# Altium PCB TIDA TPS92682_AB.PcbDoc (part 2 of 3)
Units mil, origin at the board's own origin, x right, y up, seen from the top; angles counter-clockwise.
Board outline 3149 x 2999 mil, 6 copper layers (Top Layer, Signal Layer 1, Signal Layer 2, Signal Layer 3, Signal Layer 4, Bottom Layer), stack 61.4 mil thick; 281 components, 181 nets, 796 pads, 814 vias.
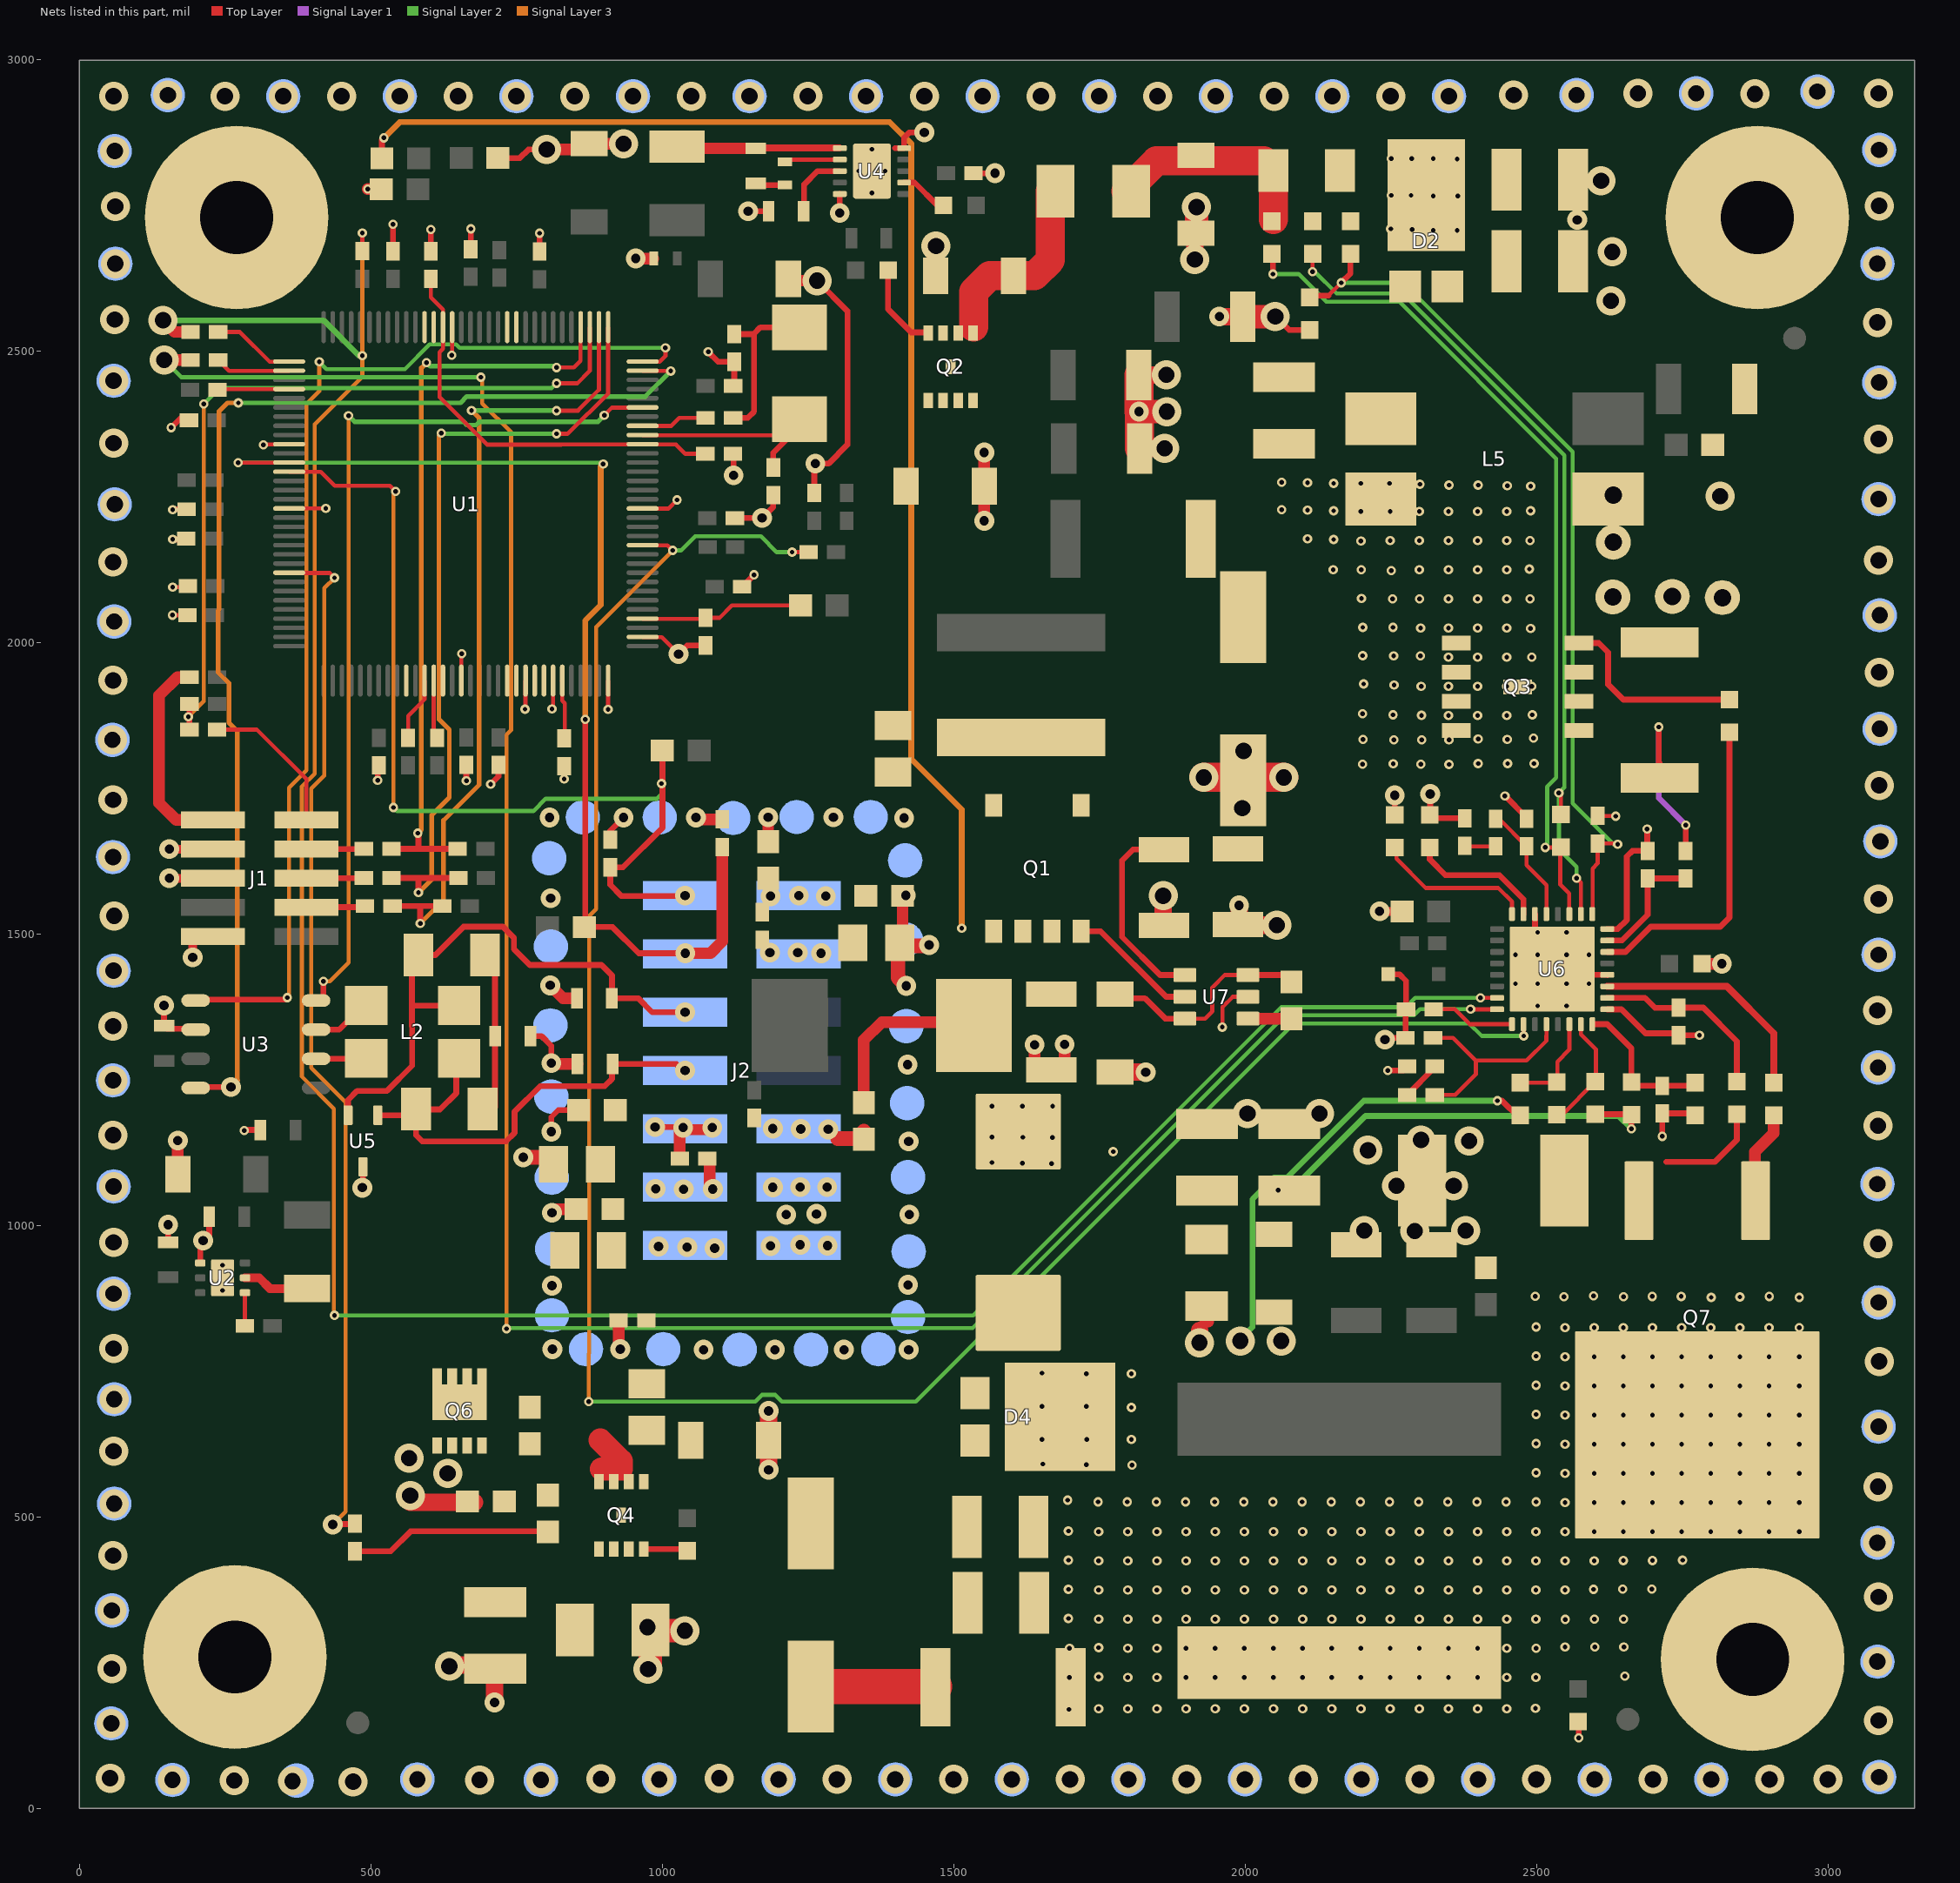
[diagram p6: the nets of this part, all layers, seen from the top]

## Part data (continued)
C90: library part CMP-0006993-4, "CAP, CERM, 1000 pF, 100 V, +/- 5%, C0G/NP0, 0603", Cap_Case=0603, Manufacturer=TDK, PartNumber=C1608C0G2A102J080AA, Supplier Part Number 1=445-2312-1-ND, TempCo=C0G/NP0, Tolerance_%=5%, Value1="0.0589 ohm", Value2=100V, ValueDisplayed=1nF
D2: library part CMP-0028754-2, "Diode, Schottky, 100 V, 3 A, AEC-Q101, PowerDI5", Manufacturer="Diodes Inc.", Value1=3A, Value2=0.76V
D3: library part CMP-0085730-1, "Diode, Zener, 3.3 V, 300 mW, AEC-Q101, SOD-323", Manufacturer="ON Semiconductor", Power_W=300mW, Value1=0.3W
D4: library part CMP-0028826-1, "Diode, Schottky, 100 V, 8 A, AEC-Q101, TO-277A", Manufacturer="Fairchild Semiconductor", Supplier Part Number 1=FSV8100VCT-ND, Value1=8A, Value2=0.67V
FID1 FID2 FID3: library part CMP-0077181-1, "Fiducial mark.  There is nothing to buy or mount.", Manufacturer=N/A
J1: library part CMP-0075629-2, "Header, 1.27mm, 5x2, Gold, Black, SMT", Color=Black, Current_A=3.3A, Manufacturer=Samtec, PartNumber=FTSH-105-01-F-DV, Supplier Part Number 1=SAM8795-ND
J2: library part CMP-0075611-2, "Header, 2.54mm, 7x2, Gold, SMT", Color=Black, Current_A=5.4A, Manufacturer=Samtec, Supplier Part Number 1=TSM-107-01-L-DV-ND
L1: library part CMP-0062763-1, "Inductor, Wirewound, Ferrite, 1 uH, 1 A, 0.06 ohm, SMD", Manufacturer=TDK, PartNumber=NLCV32T-1R0M-PF, Supplier Part Number 1=445-1534-1-ND, Value1="0.06 ohm", Value2=1A, ValueDisplayed=1uH
L2: library part CMP-0076842-1, "Coupled inductor, 100 µH, 0.15 A, 1.5 ohm, SMD", Manufacturer=TDK, PartNumber=B82789C0104H001, Supplier Part Number 1=871-B82789C0104H001, ValueDisplayed=100µH
L3: library part CMP-0058987-1, "Inductor, Shielded, 4.7 uH, 2.7 A, 0.083 ohm, AEC-Q200 Grade 1, SMD", Manufacturer="MuRata Toko", Value1="0.083 ohm", Value2=2.7A, ValueDisplayed=4.7uH
L4: library part CMP-0061052-1, "Inductor, Shielded, Composite, 3.3 uH, 15.1 A, 0.01 ohm, SMD", Manufacturer=Coilcraft, Value1="0.01 ohm", Value2=15.1A, ValueDisplayed=3.3uH
L5: library part CMP-0013101-2, "Coupled inductor, 15 uH, 6.5 A, 0.0355 ohm, SMD", Manufacturer=TDK, PartNumber=B82477D4153M000, Supplier Part Number 1=2254607, ValueDisplayed=15uH
L6 L10: library part CMP-0063280-1, "Inductor, Shielded Drum Core, Powdered Iron, 4.7 uH, 1.7 A, 0.095 ohm, SMD", Manufacturer=Vishay-Dale, Supplier Part Number 1=541-1051-1-ND, Value1="0.095 ohm", Value2=1.7A, ValueDisplayed=4.7uH
L7 L11 L12 L13 L14: library part CMP-0003297-1, "Ferrite Bead, 220 ohm @ 100 MHz, 2 A, 0805", Manufacturer="Wurth Elektronik", Supplier Part Number 1=732-6711-1-ND, Value1="0.05 ohm", Value2=2A, ValueDisplayed="220 ohm"
L8: library part CMP-0061646-2, "Inductor, Shielded, Composite, 15 uH, 18 A, 0.00917 ohm, SMD", Manufacturer=Coilcraft, Value1="0.00917 ohm", Value2=18A, ValueDisplayed=15uH
L9: library part CMP-0080422-3, "Inductor, Shielded, Ferrite, 15 µH, 3.3 A, 0.036 ohm, AEC-Q200 Grade 0, SMD", Manufacturer=TDK, Supplier Part Number 1=445-174717-1-ND, Value1="0.036 ohm", Value2=3.3A, ValueDisplayed=15µH
L15: library part CMP-0003060-1, "Ferrite Bead, 115 ohm @ 100 MHz, 10 A, SMD, 2-Leads, Body 8.74x4.65mm", Manufacturer="Laird-Signal Integrity Products", Supplier Part Number 1=240-2511-1-ND, Value1="0.001 ohm", Value2=10A, ValueDisplayed="115 ohm"
LBL1: library part CMP-0003625-1, "Thermal Transfer Printable Labels, 0.650\" W x 0.200\" H - 10,000 per roll", Manufacturer=Brady, Supplier Part Number 1=97C5133
Logo1: library part CMP-0074844-1
Logo2: library part CMP-0074838-1, "Texas Instrument Corporate Signature"
Logo3: library part CMP-0074847-1, "FCC_disclaimer"
Logo4: library part CMP-0074769-1
Logo5: library part CMP-0074836-1, "IEC 61010-1 Caution Warning"
LOGO6: library part CMP-0074837-1, "IEC 61010-1 Hot Surface Warning"
Q1: library part CMP-0077633-1, "MOSFET, N-CH, 60 V, 287 A, AEC-Q101, DFN5 5x6mm", Alternate Manufacturer=None, Manufacturer="ON Semiconductor", Supplier Part Number 1=NVMFS5C604NLT1G-ND, Value1="0.0017 ohm", Value2="52 nC"
Q2 Q4: library part CMP-0750095-1, "MOSFET, P-CH, -60 V, -6 A, AEC-Q101, 8-PowerWDFN", Alternate Manufacturer=None, Manufacturer="ON Semiconductor", Value1="0.072 ohm", Value2="14 nC"
Q3: library part CMP-0001033-3, "MOSFET, N-CH, 100 V, 20 A, AEC-Q101, 8-PowerVDFN", Alternate Manufacturer=None, Manufacturer=STMicroelectronics, Supplier Part Number 1=497-13652-1-ND, Value2="20.5 nC"
Q6: library part CMP-0000970-2, "MOSFET, N-CH, 100 V, 3.8 A, 8-PowerVDFN", Alternate Manufacturer=None, Manufacturer="Diodes Inc.", PartNumber=DMN10H120SFG-13, Supplier Part Number 1=DMN10H120SFG-13DICT-ND, Value2="10.6 nC"
Q7: library part CMP-0082013-2, "MOSFET, N-CH, 80 V, 75 A, AEC-Q101, DDPAK", Alternate Manufacturer=None, Manufacturer=Nexperia, Supplier Part Number 1=1727-1093-1-ND, Value1="? ohm", Value2="48.8 nC"
R1: library part CMP-0026763-1, "RES, 100, 1%, 0.063 W, AEC-Q200 Grade 0, 0402", Manufacturer="Stackpole Electronics Inc", Power_W=63mW, Supplier Part Number 1=RMCF0402JT100RCT-ND, TempCo="100 ppm/C", Tolerance_%=1%, Value2=0.063W, Value_Code=100R, ValueDisplayed=100
R2 R3 R8 R13 R26 R28 R44 R45 R72: library part CMP-0026754-1, "RES, 10.0 k, 1%, 0.063 W, AEC-Q200 Grade 0, 0402", Manufacturer="Stackpole Electronics Inc", Power_W=63mW, Supplier Part Number 1=RMCF0402FT10K0CT-ND, TempCo="100 ppm/C", Tolerance_%=1%, Value2=0.063W, Value_Code=10k0, ValueDisplayed=10.0k
R4 R5 R6 R7 R59 R60 R61 R62 R63 R71: library part CMP-0026759-1, "RES, 33.0, 1%, 0.063 W, AEC-Q200 Grade 0, 0402", Manufacturer="Stackpole Electronics Inc", Power_W=63mW, Supplier Part Number 1=RMCF0402FT33R0CT-ND, TempCo="100 ppm/C", Tolerance_%=1%, Value2=0.063W, Value_Code=33R0, ValueDisplayed=33.0
R9: library part CMP-0025825-4, "RES, 51, 5%, 0.1 W, AEC-Q200 Grade 0, 0603", Manufacturer=Vishay-Dale, PartNumber=CRCW060351R0JNEA, Power_W=100mW, Supplier Part Number 1=541-51GCT-ND, TempCo="200 ppm/C", Tolerance_%=5%, Value2=0.1W, Value_Code=51R0, ValueDisplayed=51
R10 R18: library part CMP-0026825-5, "RES, 10 k, 5%, 0.063 W, AEC-Q200 Grade 0, 0402", Manufacturer=Vishay-Dale, PartNumber=CRCW040210K0JNED, Power_W=63mW, Supplier Part Number 1=541-10KJCT-ND, TempCo="200 ppm/C", Tolerance_%=5%, Value2=0.063W, Value_Code=10k0, ValueDisplayed=10k
R14 R39 R43 R70: library part CMP-0025950-3, "RES, 100 k, 1%, 0.063 W, AEC-Q200 Grade 0, 0402", Manufacturer=Vishay-Dale, Power_W=63mW, Supplier Part Number 1=541-100KLCT-ND, TempCo="100 ppm/C", Tolerance_%=1%, Value2=0.063W, Value_Code=100k
R16: library part CMP-0026781-1, "RES, 4.87 k, 0.1%, 0.062 W, AEC-Q200 Grade 0, 0402", Manufacturer=Panasonic, Power_W=62mW, Supplier Part Number 1=P4.87KDCCT-ND, TempCo="25 ppm/C", Tolerance_%=0.1%, Value2=0.062W, Value_Code=4k87, ValueDisplayed=4.87k
R17: library part CMP-0026992-3, "RES, 0, 5%, 0.1 W, AEC-Q200 Grade 0, 0402", Manufacturer=Panasonic, PartNumber=ERJ-2GE0R00X, Power_W=100mW, Supplier Part Number 1=P0.0JCT-ND, TempCo="600 ppm/C", Tolerance_%=5%, Value2=0.1W, Value_Code=0000, ValueDisplayed=0
R19: library part CMP-0015792-2, "RES, 0.1, 1%, 2 W, 2512", Manufacturer="Stackpole Electronics Inc", Power_W=2W, Supplier Part Number 1=CSRN2512FTR100CT-ND, TempCo="200 ppm/C", Tolerance_%=1%, Value_Code=R100, ValueDisplayed=0.1
R20: library part CMP-0002354-3, "Thermistor NTC, 100k ohm, 1%, 0603", Manufacturer=TDK, PartNumber=NTCG164KF104F, Supplier Part Number 1=445-2556-1-ND, Tolerance_%=1%
R21 R37 R55: library part CMP-0022986-5, "RES, 2.20 k, 1%, 0.1 W, 0603", Manufacturer=Yageo, PartNumber=RC0603FR-072K2L, Power_W=100mW, Supplier Part Number 1=311-2.20KHRCT-ND, TempCo="100 ppm/C", Tolerance_%=1%, Value2=0.1W, Value_Code=2k20, ValueDisplayed=2.20k
R22 R32 R47 R50: library part CMP-0021990-4, "RES, 100 k, 1%, 0.1 W, AEC-Q200 Grade 0, 0603", Manufacturer=Vishay-Dale, PartNumber=CRCW0603100KFKEA, Power_W=100mW, Supplier Part Number 1=541-100KHCT-ND, TempCo="100 ppm/C", Tolerance_%=1%, Value2=0.1W, Value_Code=100k
R23 R25: library part CMP-0017102-3, "RES, 60.4, 1%, 0.25 W, AEC-Q200 Grade 0, 1206", Manufacturer=Vishay-Dale, PartNumber=CRCW120660R4FKEA, Power_W=250mW, Supplier Part Number 1=541-60.4FCT-ND, TempCo="100 ppm/C", Tolerance_%=1%, Value2=0.25W, Value_Code=60R4, ValueDisplayed=60.4
R24: library part CMP-0026639-2, "RES, 0.47, 1%, 0.125 W, AEC-Q200 Grade 0, 0402", Manufacturer=Panasonic, PartNumber=ERJ-2BQFR47X, Power_W=125mW, Supplier Part Number 1=P.47AKCT-ND, TempCo="250 ppm/C", Tolerance_%=1%, Value2=0.125W, Value_Code=R470, ValueDisplayed=0.47
R29 R48: library part CMP-0017279-2, "RES, 0.1, 1%, 0.5 W, 1206", Manufacturer=Panasonic, PartNumber=ERJ-8BWFR100V, Power_W=500mW, Supplier Part Number 1=1577547, TempCo="150 ppm/C", Tolerance_%=1%, Value2=0.5W, Value_Code=R100, ValueDisplayed=0.1
R30 R49: library part CMP-0025697-4, "RES, 0, 5%, 0.1 W, AEC-Q200 Grade 0, 0603", Manufacturer=Vishay-Dale, PartNumber=CRCW06030000Z0EA, Power_W=100mW, Supplier Part Number 1=541-0.0GCT-ND, TempCo="200 ppm/C", Tolerance_%=5%, Value2=0.1W, Value_Code=0000, ValueDisplayed=0
R31 R46 R54 R66: library part CMP-0025701-4, "RES, 10 k, 5%, 0.1 W, AEC-Q200 Grade 0, 0603", Manufacturer=Vishay-Dale, PartNumber=CRCW060310K0JNEA, Power_W=100mW, Supplier Part Number 1=541-10KGCT-ND, TempCo="200 ppm/C", Tolerance_%=5%, Value2=0.1W, Value_Code=10k0, ValueDisplayed=10k
R33 R34 R40 R41 R51 R52 R53: library part CMP-0022003-4, "RES, 10.0, 1%, 0.1 W, AEC-Q200 Grade 0, 0603", Manufacturer=Vishay-Dale, PartNumber=CRCW060310R0FKEA, Power_W=100mW, Supplier Part Number 1=541-10.0HCT-ND, TempCo="100 ppm/C", Tolerance_%=1%, Value2=0.1W, Value_Code=10R0, ValueDisplayed=10.0
R35: library part CMP-0022515-4, "RES, 5.90 k, 1%, 0.1 W, AEC-Q200 Grade 0, 0603", Manufacturer=Vishay-Dale, Power_W=100mW, Supplier Part Number 1=541-5.90KHCT-ND, TempCo="100 ppm/C", Tolerance_%=1%, Value2=0.1W, Value_Code=5k90, ValueDisplayed=5.90k
R36: library part CMP-0025963-3, "RES, 10.0, 1%, 0.063 W, AEC-Q200 Grade 0, 0402", Manufacturer=Vishay-Dale, Power_W=63mW, Supplier Part Number 1=541-10.0LCT-ND, TempCo="100 ppm/C", Tolerance_%=1%, Value2=0.063W, Value_Code=10R0, ValueDisplayed=10.0
R38: library part CMP-0015422-2, "RES, 0.03, 1%, 3 W, 2512", Manufacturer=Bourns, Power_W=3W, Supplier Part Number 1=652-CRA2512FZR030ELF, TempCo="75 ppm/C", Tolerance_%=1%, Value_Code=R030, ValueDisplayed=0.03
R42: library part CMP-0015521-3, "RES, 1.20, 1%, 1 W, AEC-Q200 Grade 0, 2512", Manufacturer=Vishay-Dale, Power_W=1W, Supplier Part Number 1=541-1.20AFCT-ND, TempCo="100 ppm/C", Tolerance_%=1%, Value_Code=1R20, ValueDisplayed=1.20
R56: library part CMP-0074665-1, "RES, 0.008, 1%, 2 W, AEC-Q200 Grade 0, 2512", Manufacturer=Bourns, Power_W=2W, Supplier Part Number 1=CRE2512-FZ-R008E-2CT-ND, TempCo="50 ppm/C", Tolerance_%=1%, Value_Code=8L000, ValueDisplayed=0.008
R57: library part CMP-0021990-4, "RES, 100 k, 1%, 0.1 W, AEC-Q200 Grade 0, 0603", Manufacturer=Vishay-Dale, Power_W=100mW, Supplier Part Number 1=541-100KHCT-ND, TempCo="100 ppm/C", Tolerance_%=1%, Value2=0.1W, Value_Code=100k
U1: library part CMP-0077954-1, "MSP432E401YTPDT, PDT0128A (TQFP-128)", Alternate Manufacturer="Texas Instruments", Alternate PartNumber=MSP432E401YTPDT
U2: library part CMP-0067210-5, "Automotive Catalog 5V, 400mA, 4MHz Step-Up DC/DC Converter, DRV0006A (WSON-6)", Alternate Manufacturer="Texas Instruments", PartNumber=TPS61240IDRVRQ1
U3: library part CMP-0075993-1, "Automotive Fault Protected CAN Transceiver With Flexible Data-Rate, D0008A (SOIC-8)", Alternate Manufacturer="Texas Instruments", Alternate PartNumber=TCAN1042HVDQ1
U4: library part CMP-0076338-3, "3.5V to 36V, 1A Synchronous 2.1MHz Step-Down Converter for Automotive Applications, DSX0010A (WSON-10)", Alternate Manufacturer="Texas Instruments", Operating Temperature Range="-40 to 150 C", PartNumber=LM53601NQDSXRQ1, Rating=Automotive
U5: library part CMP-0043100-2, "ESD Protection Array for AC Signal Data Interface, 2 Channels, -40 to +85 degC, 3-pin SC70 (DCK), Green (RoHS & no Sb/Br)", Breakdown Voltage(Min)(V)=+/-14, IO Capacitance(Typ)(pF)=15, IO Leakage Current(nA)=50, Manufacturer="Texas Instruments", PartNumber=TPD2E007DCKR
U6: library part CMP-0084188-2, "Dual Channel Constant Voltage and Constant Current Controller with SPI Interface, RHM0032A (VQFNP-32)", Alternate Manufacturer="Texas Instruments", Operating Temperature Range="-40 to 125 C", Rating=Automotive
U7: library part CMP-0079180-1, "Low Iq Always ON Smart Diode Controller, DBV0006A (SOT-23-6)", Alternate Manufacturer="Texas Instruments", Alternate PartNumber=LM74700QDBVRQ1
Y1: library part CMP-0004665-3, "Crystal, 25 MHz,  SMD", Frequency_Fixed=25MHz, Frequency Stability=+/-30ppm, Manufacturer=NDK, PartNumber=NX5032GA-25.000M-STD-CSK-4, Supplier Part Number 1=644-1274-1-ND
ZZ1: library part CMP-0003616-3
ZZ2: library part CMP-0077236-1
ZZ3: library part CMP-0077237-1
ZZ4: library part CMP-0077238-1

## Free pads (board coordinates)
  round 315 hole 125: 1(267,260) 1(270,2729) 1(2871,256) 1(2879,2729)
  round 60 hole 30: 1(2632,2253) 1(2819,2077) 2(2632,2172) 3(2631,2078) 4(2733,2079)

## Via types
v1: diameter 16, hole 8, Top Layer to Bottom Layer, tented both sides, 458 vias
v2: diameter 50, hole 28, Top Layer to Bottom Layer, tented both sides, 188 vias
v3: diameter 34, hole 16, Top Layer to Bottom Layer, tented both sides, 85 vias
v4: diameter 16, hole 8, Top Layer to Bottom Layer, 33 vias
v5: diameter 34, hole 16, Top Layer to Bottom Layer, tented bottom, 30 vias
v6: diameter 19.68, hole 7.87, Top Layer to Bottom Layer, 18 vias
v7: diameter 34, hole 16, Top Layer to Bottom Layer, 2 vias

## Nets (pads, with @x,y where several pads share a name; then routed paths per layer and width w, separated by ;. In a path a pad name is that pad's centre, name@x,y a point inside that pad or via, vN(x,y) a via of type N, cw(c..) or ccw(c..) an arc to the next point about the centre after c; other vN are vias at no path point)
5V: C65.1 U6.31 | length 235
  Top Layer w10: C65.1@2317,1648.5 2317,1628 2344,1601 2436.5,1601 2477.79,1559.71 U6.31@2477.79,1534.25
/HBEN: R66.2 R72.2 | length 345.1
  Top Layer w10: R72.2@473,441.38 534.38,441.38 568.5,475.5 R66.2@804,475.5
CAN_RXD: U1.95 U3.4 | length 2077.6
  Top Layer w7: U1.95@966.49,2465.84 1014.55,2465.84 v1(1014.76,2465.63)
  Top Layer w10: U3.4@212.23,1237.64 v3(260.36,1237.64)
  Signal Layer 2 w8: v1(273,2411) 654.13,2411 665.13,2422 971.13,2422 v1(1014.76,2465.63)
  Signal Layer 3 w8: 271,1714.09 271,1848.37 256.74,1862.63 256.74,1907.25 256.76,1923 256.74,1930.26 238.38,1948.62 238.38,2054.87 240,2056.49 240,2396.65 254.35,2411 v1(273,2411) ; v3@271.36,1248.64 271.36,1714.09
  Signal Layer 3 w10: v3(260.36,1237.64) v3@271.36,1248.64
CAN_STB: U1.91 U3.8 | length 1551
  Top Layer w7: v1(900.76,2389.63) 913.97,2402.84 U1.91@966.49,2402.84
  Top Layer w10: U3.8@418.93,1387.64 v1(418.93,1418.93)
  Signal Layer 2 w8: v1(462,2389) 472.37,2378.63 659.5,2378.63 665.13,2373 680.87,2373 686.32,2378.45 889.58,2378.45 v1(900.76,2389.63)
  Signal Layer 2 w10: v1@900.76,2387.76 v1(900.76,2389.63)
  Signal Layer 3 w7: v1(418.93,1418.93) 429.93,1418.93 462,1451 v1(462,2389)
CAN_TXD: U1.96 U3.1 | length 1948.8
  Top Layer w7: U1.96@966.49,2481.58 995.96,2481.58 1005.76,2491.38 v1(1005.76,2505.63)
  Top Layer w10: U3.1@199.65,1387.64 353.64,1387.64 v1(357,1391)
  Signal Layer 2 w7: v1(411.76,2481.63) 424.39,2469 558.84,2469 601.28,2511.44 646.66,2511.44 652.47,2505.63 v1(1005.76,2505.63)
  Signal Layer 3 w7: v1(357,1391) 360,1394 360,1751 390,1781 390,2409 411.76,2430.76 v1(411.76,2481.63)
CANH: C27.1 J2.6 L2.3 R23.2 U5.2 | length 1032.4
  Top Layer w10: U5.2@461.17,1189.17 461.17,1215.17 477,1231 528,1231 571.13,1274.13 571.13,1341.49 570.81,1341.81 570.81,1376.77 ; L2.3@632.72,1396.28 L2.3@651.72,1377.28 571.32,1377.28 570.81,1376.77 ; v3(1039.56,1366) 983,1366 959,1390 C27.1@914,1390 914,1429 896,1447 773,1447 746,1474 746,1493.07 726.65,1512.42 659.42,1512.42 611,1464 586.91,1464 570.81,1447.9 570.81,1376.77
CANL: C38.1 J2.8 L2.2 R25.1 U5.1 | length 795.4
  Top Layer w10: U5.1@512.35,1189.17 R25.1@577.91,1189.17 ; R25.1@577.91,1200 R25.1@577.91,1189.17 ; R25.1@595.31,1199 619,1199 647,1227 647,1282 L2.2@651.72,1286.72 ; v3@1037.56,1264 1024.56,1277 C38.1@915,1277 914,1276 914,1251.62 901.38,1239 790.7,1239 747,1195.3 747,1159 732.32,1144.32 588.74,1144.32 577.91,1155.14 R25.1@577.91,1189.17
  other v3: 1039.56,1266
CSN1: C57.2 R34.1 U6.27 | length 1475.4
  Top Layer w7: R34.1@2046,2666.57 R34.1@2048,2664.57 ; v1(2515,1648.5) C57.2@2541.5,1648.5 ; C57.2@2542,1649 C57.2@2541.5,1648.5 ; U6.27@2556.53,1534.25 2556.37,1534.4 2556.37,1569.53 2541,1584.9 2541,1648 C57.2@2541.5,1648.5
  Top Layer w10: v1(2048,2632) R34.1@2048,2664.57
  Signal Layer 2 w7: v1(2048,2632) 2092.03,2632 2139.53,2584.5 2264.9,2584.5 2534,2315.4 2534,1768.2 2518.38,1752.57 2518.38,1651.88 v1(2515,1648.5)
CSN2: C73.2 R52.1 U6.14 | length 171.6
  Top Layer w7: R52.1@2472,1245 2534,1245 C73.2@2535,1246 2536,1247 2536,1281 2556.53,1301.53 U6.14@2556.53,1345.27
CSP1: C57.1 R33.1 U6.26 | length 1449.9
  Top Layer w7: v1(2116,2636) R33.1@2116,2666.57 ; v1(2538.53,1742) 2542,1738.53 C57.1@2542,1705 2543,1704 C57.1@2547,1708 ; v1@2568.87,1591.13 v1(2568.87,1595.92) 2576.43,1588.36 2576.43,1534.47 U6.26@2576.21,1534.25
  Signal Layer 2 w7: v1(2116,2636) 2119.84,2636 2157.34,2598.5 2270.7,2598.5 2548,2321.2 2548,1751.47 v1(2538.53,1742) 2538.53,1645.72 2568.87,1615.37 v1(2568.87,1595.92)
CSP2: C73.1 R51.1 U6.15 | length 199
  Top Layer w7: C73.1@2535,1190 2544,1190 R51.1@2601,1247 2602,1248 2602,1302.31 2576.21,1328.1 U6.15@2576.21,1345.27
DRL+: C15.1 C52.1 J2.1 L7.1
  other v5: 1186,1565 1281,1565 1234.44,1566
DRL-: C18.1 C52.2 J2.3 L13.1
  other v3: 1272.81,1467 1185,1468 1232.65,1468
DRL_TEMP: C22.1 J2.2 R46.1 U1.13 | length 1642.9
  Top Layer w7: U1.13@360.24,2292.97 414.28,2292.97 438.25,2269 533,2269 v1(543,2259)
  Top Layer w10: R46.1@1000.5,1815 1000.5,1682.02 932.86,1614.38 C22.1@910.99,1614.38 910.99,1584.51 930.5,1565 1038.56,1565 v5(1039.56,1566)
  Signal Layer 2 w7: v1(539,1717) 545,1711 779.11,1711 800.11,1732 991.16,1732 999,1739.84 v1(999,1758)
  Signal Layer 3 w7: v1(539,1717) v1@539,2253
EN: R22.1 U4.7 | length 83.8
  Top Layer w10: U4.7@1415.12,2788.94 1433.06,2788.94 1472.1,2749.9 R22.1@1482.76,2749.9
ENETLED0: U1.42
ENETLED1: U1.46
EPHYRX_N: U1.53
EPHYRX_P: U1.54
EPHYTX_N: U1.56
EPHYTX_P: U1.57
FB1: C58.1 R32.1 R37.2 U6.25 | length 1509
  Top Layer w7: R37.2@2111,2592 R37.2@2114,2595 ; 2143,2595 v1(2165,2617) ; U6.25@2595.9,1534.25 2596.37,1534.72 2596.37,1612.37 2605,1621 C58.1@2605,1655.38 2638.06,1655.38 v1(2639.44,1654)
  Top Layer w10: R37.2@2114,2595 2143,2595 ; v1(2165,2617) 2181,2633 R32.1@2181,2666.57
  Signal Layer 2 w7: v1(2165,2617) 2272,2617 2562,2327 2562,1724 2632,1654 v1(2639.44,1654) ; v1@2637,1655 v1@2639,1655
FB2: C76.1 R50.1 R55.2 U6.16 | length 255.9
  Top Layer w10: U6.16@2595.9,1345.27 2621.5,1345.27 2663,1303.77 R50.1@2663,1246 2669.38,1239.62 C76.1@2716,1239.62 2766.62,1239.62 R55.2@2772,1245
GND: C1.2 C2.2 C3.2 C4.2 C5.2 C6.2 C7.2 C8.2 C9.2 C10.2 C11.2 C12.2 C13.2 C14.2 C15.2 C16.2 C17.2 C18.2 C19.2 C20.2 C21.2 C22.2 C23.2 C24.2 C25.2 C26.2 C27.2 C28.2 C30.2 C31.2 C32.2 C34.2 C35.2 C36.2 C37.2 C38.2 C39.2 C41.2 C42.2 C43.2 C44.2 C45.2 C46.2 C47.2 C48.2 C50.1 C51.1 C53.1 C54.2 C55.1 C56.2 C58.2 C59.1 C60.1 C62.2 C63.2 C65.2 C66.2 C67.1 C68.2 C69.2 C70.2 C71.2 C72.1 C74.2 C75.1 C76.2 C79.2 C80.1 C81.2 C82.2 C84.2 C85.2 C86.2 C89.2 C90.1 D3.2 Designator11.1@3090,1659 Designator12.1@3089,1852 Designator13.1@3087,1464.56 Designator14.1@1418.83,1342 Designator15.1@1418,1490.38 Designator16.1@1417,1626.19 Designator17.1@1357.92,1700.69 Designator18.1@1231,1700.69 Designator19.1@1121.96,1699 Designator20.1@996,1700.02 Designator21.1@864,1700.02 Designator22.1@806.26,1630 Designator23.1@809.14,1478.5 Designator24.1@808.42,1343.32 Designator25.1@810,1221 Designator26.1@810.69,1082 Designator27.1@811.52,960 Designator28.1@811,846 Designator29.1@869.45,788 Designator30.1@1002,788 Designator31.1@1133,787.2 Designator32.1@1255.46,787.2 Designator33.1@1371,788 Designator34.1@1422,843 Designator35.1@1423,955.7 Designator36.1@1422,1083 Designator37.1@1420.48,1210 Designator38.1@3088,54 Designator39.1@3085,252 Designator40.1@3085,456 Designator41.1@3087,654.98 Designator42.1@3087,868 Designator43.1@3085,1071.26 Designator44.1@3086,1271.24 Designator45.1@3089,2046.76 Designator46.1@3087,2246 Designator47.1@3088,2446 Designator48.1@3085,2649.81 Designator49.1@3088,2845 Designator50.1@2982,2945 Designator51.1@2774,2942 Designator52.1@2568.87,2939 Designator53.1@2350,2937 Designator54.1@2150,2937 Designator55.1@1950,2937 Designator56.1@1750,2937 Designator57.1@1550,2937 Designator58.1@1350,2937 Designator59.1@1150,2937 Designator60.1@950,2937 Designator61.1@750,2937 Designator62.1@550,2937 Designator63.1@350,2937 Designator64.1@152,2939 Designator65.1@61,2843 Designator66.1@62,2649.81 Designator67.1@59,2449 Designator68.1@61,2237 Designator69.1@60,2036 Designator70.1@57,1833 Designator71.1@58,1632 Designator72.1@59,1437 Designator73.1@58,1249 Designator74.1@59,1067 Designator75.1@59,883 Designator76.1@60,702 Designator77.1@60,523 Designator78.1@56,340 Designator79.1@55,146 Designator80.1@160,49 Designator81.1@373,48 Designator82.1@580,50 Designator83.1@791.94,49 Designator84.1@995,50 Designator85.1@1200,50 Designator86.1@1400,50 Designator87.1@1600,50 Designator88.1@1800,50 Designator89.1@2000,50 Designator90.1@2200,50 Designator91.1@2400,50 Designator92.1@2600,50 Designator93.1@2800,50 J1.3 J1.5 J1.9 J2.9 J2.11 J2.13 L5.1 L9.2 L13.2 L14.2 pad.1 pad.2 pad.3 pad.4 Q6.1 Q6.2 Q6.3 R16.2 R20.1 R35.1 R37.1 R38.1 R43.2 R47.1 R55.1 R56.1 R57.1 R70.1 U1.10 U1.17 U1.48 U1.55 U1.58 U1.64 U1.66 U1.80 U1.114 U2.1 U2.7@246,910.28 U3.2 U4.5 U4.10 U4.11@1360,2808.63 U5.3 U6.17 U6.20 U6.24 U6.30 U6.33 U7.2 | length 6392.2
  Top Layer w7: v1(160.17,2047) C5.2@185.76,2047 ; v1(160.38,2095) C2.2@185.76,2095 ; v1@316.85,2339.85 U1.10@360.19,2339.85 ; U1.17@360.19,2229.61 360.55,2229.98 v1(423,2229.98) ; v1@639.77,2493.71 U1.114@639.77,2541 ; U1.48@655.46,1934.34 v1@655.46,1981.33 ; v1(764.76,1885.63) 765.7,1886.57 U1.55@765.7,1934.34 ; v1(811,1886) v1@812.13,1886 ; v1@812.94,1886.81 U1.58@812.94,1934.34 ; v1(907.43,1885.41) U1.64@907.43,1934.34 ; U1.66@966.49,2009.14 999.46,2009.14 v3(1028.34,1980.27) ; U1.80@966.49,2229.61 1010.74,2229.61 v1(1025.76,2244.63) ; C11.2@1121.2,2441.03 C11.2@1121.96,2440.27 ; v1(1960.96,1340.31) 1961.41,1340.76 1961.41,1374.76 1978.96,1392.31 U7.2@2005.1,1392.31 ; C58.2@2605,1702.62 2635.38,1702.62 v1(2636,1702)
  Top Layer w10: v3@150.58,1382.64 v3(145.58,1377.64) C30.2@145.58,1342.64 150.58,1337.64 U3.2@199.65,1337.64 ; C25.2@152.42,971.36 v3(152.42,1001.36) ; v1(157.76,2368.63) 173.62,2384.49 C3.2@189.72,2384.49 ; v1@162.52,2176.86 C4.2@184.34,2176.86 ; v1@163.71,2228.67 C81.2@184.33,2228.67 ; J1.9@194.58,1495.64 J1.9@229.46,1495.64 ; U2.1@207.61,935.87 207.61,968.86 v3(212.76,974) 223,984.24 C23.2@223,1015 ; v1(283.31,1163) 284.31,1164 C31.2@311,1164 ; v1(316,2339) v1@316.85,2339.85 ; v3(485.76,1065) 486.76,1066 U5.3@486.76,1100.59 ; v1(512,1763.86) 512,1787.22 C6.2@514.23,1789.45 ; C14.2@538.34,2671.11 v1(538.34,2717.49) ; C16.2@603.34,2671.11 v1(603.34,2708.49) ; v1(639,2492.94) v1@639.77,2493.71 ; v1(664.23,1763) C7.2@664.23,1789.45 ; C13.2@671.76,2674.44 v1(671.76,2709.44) ; v1(705.93,1757) 719.23,1770.3 C8.2@719.23,1789.45 ; C80.1@718.45,2831 756.04,2831 770.66,2845.62 v2(802,2845.62) ; C28.2@774,1325 793,1325 810,1308 v5(810,1278.52) v5@811.52,1277 ; C12.2@789.76,2670.44 v1(789.76,2702.07) ; v3(810,1161) 810,1186 822,1198 C84.2@856.65,1198 ; v3@811,1029 v3(811,1022) v3@817,1028 ; L14.2@811.87,1116.91 812,1116.78 812,1110 L14.2@817,1105 ; v1@812.13,1886 v1@812.94,1886.81 ; v1(832,1766) R16.2@832,1788.19 R16.2@832,1795.19 ; C22.2@910.99,1661.62 910.99,1677.16 v3(933.83,1700) ; v3@925.55,790.76 v3(928.31,788) ; v3(1028.34,1980.27) 1043.08,1995.01 C19.2@1074.76,1995.01 ; v5(1058.13,1700) v5@1061.5,1696.62 ; v1(1079.14,2498.63) 1096.18,2481.58 C26.2@1123.76,2481.58 1123.76,2442.06 C11.2@1121.96,2440.27 ; C17.2@1121.38,2323.63 1122.76,2322.25 v5(1122.76,2286.63) ; C10.2@1124.96,2213.49 v3(1171.56,2213.49) 1190.76,2232.69 C24.2@1190.76,2253.01 ; C9.2@1137.38,2095.63 v1(1157.88,2116.13) ; v3(1147.76,2739.63) C39.2@1182.76,2739.63 ; C20.2@1254.38,2249.72 C20.2@1261,2256.34 1261,2304.8 v3(1263,2306.8) 1285.55,2306.8 1318,2339.25 1318,2568.7 v2(1266,2620.7) ; v3(1285,1165) 1301,1149 ; v3(1304.64,2736.62) U4.5@1304.64,2769.26 ; 1399.37,2848 U4.10@1415.12,2848 1415.12,2865.79 1424.33,2875 v3(1450,2875) v3@1450,2865.61 ; C18.2@1402,1553.5 C18.2@1404.93,1553.5 ; L13.2@1404.67,1479.75 L13.2@1412.5,1487.58 ; v5@1456.6,1479.75 v5(1458,1481.15) ; C34.2@1534.39,2804.9 v3(1571,2804.9) v3@1571,2796.28 ; C46.2@1639.13,1267.04 C46.2@1668,1267.04 C46.2@1690.7,1267.04 ; v2(2052,2559) 2053,2559 2076,2536 R37.1@2111,2536 ; v5(2240,1319) 2240,1322 C71.2@2275.38,1322 2275.38,1370 R43.2@2276.38,1371 2276.38,1419.62 2265,1431 D3.2@2245.69,1431 ; v1(2244.82,1266) 2271.38,1266 C86.2@2278.38,1273 ; R47.1@2257,1704.5 v3(2257,1738) ; R56.1@2300.95,1056.05 R56.1@2300.95,1058 ; v3(2317.88,1740) 2317.88,1707.39 2316,1705.5 C65.2@2317,1704.5 2322.88,1698.62 R70.1@2377,1698.62 ; v1(2446,1737) 2483,1700 C50.1@2483,1697.62 ; U6.30@2497.47,1534.25 2497.47,1469.29 v6(2502.2,1464.56) U6.33@2527,1439.76 2536.84,1429.92 U6.20@2621.49,1429.92 U6.20@2621.65,1429.76 ; R20.1@2571.49,149.33 2569.79,147.63 2572.7,144.72 v1(2572.7,121) ; U6.17@2621.49,1370.86 2645.9,1370.86 2687,1329.76 C75.1@2740.62,1329.76 ; U6.24@2621.49,1508.66 2639.66,1508.66 2655,1524 2655,1633 2664.62,1642.62 C60.1@2691,1642.62 ; C60.1@2690,1643.62 v1(2690,1680) ; v1(2716,1153) C76.2@2716,1192.38 R55.1@2768.62,1192.38 ; C75.1@2744,1326.38 v1(2779.62,1326.38)
  Top Layer w15: v3(154.58,1595.64) J1.5@229.46,1595.64 ; v3(154.58,1645.64) J1.3@229.46,1645.64 ; v3(194.58,1459.96) J1.9@194.58,1495.64 ; v3(2231,1539) C59.1@2269.5,1539
  Top Layer w20: C89.2@169.14,1088 v7(169.14,1145.86) ; v1@494.76,2777.63 v1(495.2,2777.63) R35.1@518.26,2777.63 ; v2(802,2845.62) 864.82,2845.62 C37.2@874.76,2855.56 v2(933.83,2855.56) ; v5(808,1412) 830,1390 C27.2@854,1390 ; v5@811.52,1277 C38.2@855,1277 ; v3@817,1028 C82.2@852.5,1028 ; v3@925.55,790.76 C66.2@925.55,837 ; v3(954.76,2658.63) C35.2@984.76,2658.63 ; v5@1061.5,1696.62 C1.2@1103.26,1696.62 ; C15.2@1182,1658.5 v3(1182,1700.24) ; C70.2@1182.76,634 1180.76,632 C70.2@1183.69,629.07 ; C36.2@1216.69,2623.63 1219.62,2620.7 v2(1266,2620.7) ; L13.2@1412.5,1487.58 C18.2@1412.5,1565.71 ; v5(1552.69,2208.69) C56.2@1552.69,2268 v5(1552.69,2325.8) ; C46.2@1639.13,1267.04 v3(1639.13,1310.13) ; C46.2@1690.7,1267.04 v3(1690.7,1310.84) ; C74.2@2784,1449 v3(2818,1449)
  Top Layer w25: v3(762,1116.91) L14.2@811.87,1116.91 ; 1301,1149 1333,1149 C90.1@1346,1162 ; v5(1419,1411) 1404.67,1425.33 1404.67,1479.75 v5@1456.6,1479.75
  Top Layer w30: v2@568,525 R57.1@678.5,525 ; v2@649,246 742.95,246 C69.2@743,245.95 ; v5(712.74,181.96) C69.2@712.74,240.91 ; C69.2@726,249.95 C69.2@727,248.95 ; v3(1182.76,581.07) C70.2@1183.69,629.07 ; C70.2@1182.76,634 v3(1182.76,682.07) ; C55.1@1469.07,2629 1469.07,2680.07 1469.93,2680.07 v2(1470,2680) ; C45.2@1777,1263.07 v3(1829.86,1263.07) ; v3(1818,2396) v3(1818,2396) ; C32.2@1817.96,2459 v2(1865,2459) ; C48.2@1818.96,2333 v2(1862,2333) ; C43.2@1849.61,1516.88 1859.61,1526.88 v2(1859.61,1565.71) ; v2(1914,2657) C79.2@1914,2686 ; v3(1956,2559) C44.2@1995.96,2559 ; v3(1989.87,1549.22) 1989.87,1530.89 1993.19,1527.58 1981.87,1516.26 1982.91,1515.22 v2(2054.87,1515.22)
  Top Layer w40: v3(1818,2396) v2(1866,2396) ; C79.2@1916,2711.91 1917,2712.91 v2(1917,2747) ; C44.2@1995.96,2559 v2(2052,2559)
  Top Layer w50: v3(1818,2396) C32.2@1817.96,2459 ; C48.2@1818.96,2333 v3@1818.96,2395.04 ; v2(1929.39,1768.69) v2(2066.61,1768.69)
  other v1: 1773.89,1126.66 656.2,1980.63 160.38,2177 160.38,2228
  other v2: 470,46 366,47 266,48 160,49 687,49 791.94,49 580,50 995,50 1200,50 1300,50 1400,50 1500,50 1600,50 1700,50 1800,50 1900,50 2000,50 2100,50 2200,50 2300,50 2400,50 2500,50 2600,50 2700,50 2800,50 2900,50 3000,50 895,51 53,52 1098,52 3088,54 55,146 3087,151 56,240 635,244 3085,252 56,340 3087,363 58,434 3085,456 60,523 568,537 3086,552 632,575 566,601 59,613 3087,654.98 60,702 3088,767 59,789 3087,868 59,883 3086,968.73 59,971 2204.84,991.26 2291.35,990.54 2378.59,991.26 59,1067 2260,1068 2358,1068 3085,1071.26 2211,1129 2384.4,1145 2302,1146.88 58,1155 3086,1171.18 2004.18,1192 2128,1192 58,1249 3086,1271.24 58,1342 3085,1369 59,1437 3087,1464.56 60,1531.05 3087,1560 58,1632 3090,1659 1995.46,1716 58,1730 3088,1755 1997.64,1814 57,1833 3089,1852 58,1935 3088,1949 60,2036 3089,2046.76 58,2138 3087,2141 61,2237 3087,2246 2815,2251 59,2342 3087,2349 3088,2446 59,2449 3085,2549 61,2554 2628,2586 62,2649.81 3085,2649.81 2630,2670 62,2748 3088,2749 2611,2792 61,2843 3088,2845 59,2937 250,2937 350,2937 450,2937 550,2937 650,2937 750,2937 850,2937 950,2937 1050,2937 1150,2937 1250,2937 1350,2937 1450,2937 1550,2937 1650,2937 1750,2937 1850,2937 1950,2937 2050,2937 2150,2937 2250,2937 2350,2937 152,2939 2461,2939 2568.87,2939 2875,2941 2674,2942 2774,2942 3087,2942 2982,2945
  other v3: 812,788 811,897 1186,965 1284,965.46 1237,967 1213.07,1018.71 1264.89,1019.86 1190,1065.46 1237,1066 1283,1066 1190,1166.24 1238,1165.62 2570,2725
  other v4: 1668,1106 1618,1107 1566,1108 1618.87,1151.46 1669.5,1151 1566,1152 1566,1204.62 1618,1204.62 1670,1204.62
  other v5: 1071,787 1193.65,787 1312,787 1423,787 1422,898.21 1424,1019 1423,1144.32 1421,1276 809,1561.5 1418,1566.27 1415.12,1699 807,1700 1294,1700.24
  other v6: 246,888.63 246,931.94 2502.2,1376.77 2551.8,1376.77 2464.01,1414.96 2502.2,1414.96 2551.8,1414.96 2589.99,1414.96 2464.01,1464.56 2551.8,1464.56 2589.99,1464.56 2502.2,1502.75 2551.8,1502.75 1360,2771.23 1337.36,2808.63 1382.64,2808.63 1360,2846.03
GPIOSW1: U1.107
GPIOSW2: U1.108
GPLED0: U1.116
GPLED1: U1.117
HB/LB_TEMP: C1.1 J2.4 R54.1 U1.12 | length 1948.1
  Top Layer w7: v1(272.76,2308.35) U1.12@360.19,2308.35
  Top Layer w10: v1(868.12,1868) 868.12,1513.68 R54.1@866.5,1512.05 914.95,1512.05 960,1467 v5(1039.86,1467)
  Top Layer w20: v5(1039.86,1467) 1082.88,1467 1103.26,1487.38 C1.1@1103.26,1649.38
  Signal Layer 2 w7: v1(272.76,2308.35) 897,2308.35 v1(899,2306.35)
  Signal Layer 3 w10: v1(868.12,1868) 868.12,2037.71 894.76,2064.35 894.76,2302.11 v1(899,2306.35)
HB_CATHODE: C77.2 C84.1 J2.10 L14.1 | length 215.7
  Top Layer w10: v3(988,1169) 1075.13,1169 1081.13,1163 1086,1167.87 v3(1086,1168) 1086,1166 1083,1163 1080,1160 1036,1160 v3@1030.38,1165.62
  Top Layer w20: C77.2@1030.38,1115 v3@1030.38,1165.62
  other v3: 1036,1168
HB_LB_TAP: C77.1 C82.1 J2.12 L12.2 | length 49.8
  Top Layer w20: C77.1@1081.62,1112 1081.62,1062.69 v3@1082,1062.32
  other v3: 1037,1062.32 988.89,1063 1087,1062.69
JTAG_TCK: R3.1 R5.2 U1.100 | length 1287.6
  Top Layer w7: v1(818.76,2471.63) 848.76,2471.63 860.19,2483.06 U1.100@860.19,2540.64
  Top Layer w10: R5.2@535.55,1646 582.05,1646 ; v1(581.05,1673) 578.93,1673 582.05,1669.88 582.05,1646 ; R3.1@649.43,1646 582.05,1646
  Signal Layer 2 w8: v1(596,2480) 602.16,2473.84 656.16,2473.84 656.32,2474 816.39,2474 v1(818.76,2471.63)
  Signal Layer 3 w8: v1(581.05,1673) 587,1678.95 587,2471 v1(596,2480)
JTAG_TDI: R7.2 R13.1 U1.98 | length 1383.4
  Top Layer w7: v1(818.76,2397.63) 855.76,2397.63 891.68,2433.56 U1.98@891.68,2540.64
  Top Layer w10: R7.2@537.52,1548.12 585.12,1548.12 ; v1(585.12,1518.12) 585.12,1548.12 ; R13.1@622.87,1548.12 585.12,1548.12
  Signal Layer 2 w8: v1(673,2398) 818.39,2398 v1(818.76,2397.63)
  Signal Layer 3 w8: v1(585.12,1518.12) 625,1558 625,1695 686.24,1756.24 686.24,2384.76 v1(673,2398)
JTAG_TDO: R6.2 R8.1 U1.97 | length 1388.3
  Top Layer w7: v1(819,2358) 837.73,2358 838.93,2359.2 839.13,2359 907.43,2427.3 U1.97@907.43,2540.64
  Top Layer w10: R6.2@535.55,1596 582.05,1596 ; v1(582.05,1571) 582.05,1596 ; R8.1@650.43,1596 582.05,1596
  Signal Layer 2 w7: v1(621,2359.2) 622.2,2358 v1(819,2358)
  Signal Layer 3 w8: v1(582.05,1571) 605,1593.95 605,1704.28 635,1734.28 635,1850.31 617,1868.31 617,2355.2 v1(621,2359.2)
JTAG_TMS: R2.1 R4.2 U1.99 | length 1351.9
  Top Layer w7: v1(818.76,2444.63) 854.76,2444.63 875.93,2465.81 U1.99@875.93,2540.64
  Top Layer w10: R4.2@189.14,1850.63 R2.1@189.14,1894.63
  Signal Layer 2 w7: v1(213.76,2409) 241.26,2436.5 810.63,2436.5 v1(818.76,2444.63)
  Signal Layer 3 w7: v1(187.2,1872.63) 213.76,1899.19 v1(213.76,2409)
LB_ANODE: C66.1 J2.14 L11.1
  other v3: 1090.14,961 1043,963 994,964
MISO: R26.1 R61.1 U6.7 | length 4597.9
  Top Layer w7: R26.1@485.76,2671.25 v1(485.76,2702.63) ; v1(2404,1390.55) U6.7@2432.51,1390.55
  Top Layer w20: v2(143.76,2552.63) 163.76,2532.63 R61.1@191.14,2532.63
  Signal Layer 2 w7: v1(438,846) 1533.73,846 2062.23,1374.5 2276.1,1374.5 2292.15,1390.55 v1(2404,1390.55)
  Signal Layer 2 w10: v2(143.76,2552.63) 419.13,2552.63 479.76,2492 v1(485.76,2492)
  Signal Layer 3 w7: v1(438,846) 437,847 437,1200.38 382,1255.38 382,1753.2 404,1775.2 404,2374.33 486.76,2457.09 485.76,2458.09 v1(485.76,2492) v1(485.76,2702.63)
MOSI: R62.1 U6.8 | length 4186.8
  Top Layer w7: v1@2387.14,1370.86 U6.8@2432.51,1370.86
  Top Layer w10: v2(145.76,2484.63) v2@155.76,2474.63
  Top Layer w20: v2@156.76,2484.63 R62.1@191.14,2484.63
  Signal Layer 2 w7: v2(145.76,2484.63) 175.39,2455 v1(689,2455) ; v1@733,824 1532.73,824 2069.23,1360.5 2289.5,1360.5 2300,1371 v1(2387,1371)
  Signal Layer 3 w7: v1(689,2455) 691.5,2452.5 691.5,2410.13 741,2360.63 741,1850 733,1842 v1(733,823)
NetC16_1: C16.1 C17.1 U1.87 U1.115 | length 711.2
  Top Layer w7: C16.1@603.34,2623.87 603.34,2591.89 623.97,2571.26 623.97,2504.07 618,2498.1 618,2420.84 699.34,2339.5 826.66,2339.5 827.01,2339.85 1024.25,2339.85 1024.25,2339.13 1039.76,2323.63 C17.1@1074.14,2323.63
NetC19_1: C19.1 R9.2 U1.68 | length 278.3
  Top Layer w7: U1.68@966.49,2040.64 C19.1@1073.14,2040.64 ; C19.1@1074.76,2042.25 1098.38,2042.25 1119.76,2063.63 R9.2@1237.5,2063.63
NetC24_1: C24.1 U1.88 Y1.2 | length 382.3
  Top Layer w7: U1.88@966.49,2355.6 1208.18,2355.6 Y1.2@1235.76,2383.18
  Top Layer w10: C24.1@1190.76,2300.25 1190.76,2325.63 1235.76,2370.63 Y1.2@1235.76,2383.18
NetC26_1: C26.1 R17.2 Y1.1 | length 290.3
  Top Layer w10: R17.2@1121.96,2385.27 1146.88,2385.27 1157.88,2396.26 1157.88,2527.9 1156.96,2528.83 ; C26.1@1123.76,2528.83 1156.96,2528.83 ; Y1.1@1235.76,2540.66 1168.79,2540.66 1156.96,2528.83
NetC28_1: C28.1 R23.1 R25.2 | length 279
  Top Layer w10: R23.1@701.09,1464 713.45,1464 713.45,1202.97 R25.2@709.48,1199
NetC29_1: C29.1 R24.2 | length 51.2
  Top Layer w10: C29.1@1160.76,2787.63 1163.76,2784.63 R24.2@1210.76,2784.63
NetC29_2: C29.2 L3.1 U4.1 | length 279.8
  Top Layer w12: C29.2@1161.13,2848 U4.1@1304.64,2848
  Top Layer w15: L3.1@1025.76,2850.62 L3.1@1028.75,2847.63
  Top Layer w20: L3.1@1028.75,2847.63 C29.2@1160.76,2847.63
NetC39_1: C39.1 U4.3 | length 116.8
  Top Layer w10: C39.1@1242.76,2739.63 1243.76,2740.63 1243.76,2785.63 1266.76,2808.63 U4.3@1304.64,2808.63
NetC40_1: C40.1 U7.1 | length 74.9
  Top Layer w20: U7.1@2005.1,1354.91 2079.87,1354.91 C40.1@2079.96,1354.81
NetC40_2: C40.2 C45.1 C46.1 C90.2 L15.2 Q1.1 Q1.2 Q1.3 R31.2 U7.3 U7.6 | length 3042.9
  Top Layer w7: U7.6@1896.83,1354.91 1931.56,1354.91 1943.96,1367.31 1943.96,1408.31 1965.37,1429.71 U7.3@2005.1,1429.71
  Top Layer w10: R31.2@522.76,2834.13 R31.2@519.26,2830.63 519.26,2862.13 v1(522.76,2865.63) ; L15.2@1529.5,1348.89 L15.2@1535.07,1343.32 ; C45.1@1777,1389.93 1828.07,1389.93 1863.09,1354.91 U7.6@1896.83,1354.91 ; U7.3@2005.1,1429.71 2068.06,1429.71 C40.2@2079.96,1417.8
  Top Layer w20: C90.2@1346,1210.8 1346,1318 1376.89,1348.89 L15.2@1529.5,1348.89
  Signal Layer 3 w10: v1(522.76,2865.63) 549.69,2892.56 1390.61,2892.56 1427.51,2855.66 1427.51,1800.17 1514,1713.68 v1(1514,1510)
NetC41_1: C41.1 R19.1
NetC42_1: C42.1 C43.1 L4.1 Q1.5 Q1.6 U7.4 | length 345.8
  Top Layer w10: C43.1@1861.13,1644.96 1807.98,1644.96 1789,1625.98 1789,1495 1854.29,1429.71 U7.4@1896.83,1429.71
NetC49_1: C49.1 L5.4 Q3.5 Q3.6 Q3.7 Q3.8 Q3.9
  other v1: 2201.66,1791.1 2301.64,1791.1 2350,1791 2254.27,1792 2400,1792.41 2450.56,1792.41 2496,1792.41 2255.36,1833 2303.34,1833 2350,1833 2202.29,1834 2450,1834 2400,1834.72 2494.81,1836 2302.8,1875.1 2349,1875 2399,1875 2449,1875 2254,1876 2493,1876 2201.66,1878 2302.22,1925 2349,1925 2399,1925 2449,1925 2492,1925 2255.91,1927 2203.57,1929 2349,1975 2399,1975 2449,1975 2492,1975 2255,1977 2300.99,1977 2201.93,1977.53 2490,2024 2301.35,2025 2349,2025 2399,2025 2449,2025 2202,2026 2254,2026 2253,2075 2299.5,2075 2349,2075 2399,2075 2449,2075 2489,2075 2199.93,2075.53 2251,2123.22 2151.32,2125 2199.32,2125 2299,2125 2349,2125 2399,2125 2449,2125 2488,2126 2199,2174 2249,2175 2299,2175 2349,2175 2399,2175 2449,2175 2489,2175 2152,2176.65 2107.38,2177.65 2199,2225 2249,2225 2299,2225 2349,2225 2399,2225 2449,2225 2152,2226 2490,2226 2107.38,2227 2063,2228 2490.08,2268 2450,2269 2350,2270 2400,2270 2300,2271.47 2152,2273 2199,2273 2248,2273 2107.38,2274 2063,2275
NetC49_2: C49.2 D2.1 D2.2 L5.3
NetC50_2: C50.2 C87.2 U6.29 | length 202.8
  Top Layer w7: C87.2@2430,1697.62 2435.76,1697.62 C50.2@2483,1650.38 2483,1618 2517.16,1583.84 U6.29@2517.16,1534.25
NetC53_2: C53.2 C54.1 D2.3 R29.1 R32.2 R33.2
  other v4: 2323,2707.15 2364,2707.15 2287,2708.49 2250,2709.44 2323,2766 2365,2766 2251,2767 2285,2766.95 2364,2829.26 2251,2830 2286,2830 2323,2830
NetC55_2: C55.2 L6.2 Q2.1 Q2.2 Q2.3 | length 332.6
  Top Layer w50: Q2.1@1534.39,2541 1534.39,2601.39 1562,2629 C55.2@1602.93,2629 1639,2629 1666.04,2656.04 L6.2@1666.04,2774
NetC56_1: C56.1 L7.2 Q2.5 Q2.6 Q2.7 Q2.8 Q2.9
NetC60_2: C60.2 R36.2 U6.23 | length 215.1
  Top Layer w10: U6.23@2621.49,1488.97 2646.97,1488.97 2691,1533 C60.2@2691,1595.38 R36.2@2756,1595.38
NetC61_1: C61.1 R42.2 | length 214.4
  Top Layer w10: R42.2@1467.62,209.24 R42.2@1468.86,208
  Top Layer w60: C61.1@1255,209.24 R42.2@1467.62,209.24
NetC61_2: C61.2 C64.2 C88.2 D4.1 D4.2 L9.1
NetC64_1: C64.1 C88.1 L8.2 Q7.2 R42.1
  other v1: 1698,170 1749,171 1799,171 1849,171 1899,171 1949,171 1999,171 2049,171 2099,171 2149,171 2199,171 2249,171 2299,171 2349,171 2399,171 2449,171 2498.27,172 1699,225 1799,225 1849,225 1899,225 1949,225 1999,225 2049,225 2099,225 2149,225 2199,225 2249,225 2299,225 2349,225 2399,225 2449,225 2499,225 1749,226 2651.58,227 1699,275 1799,275 1849,275 1899,275 1949,275 1999,275 2049,275 2099,275 2149,275 2199,275 2249,275 2299,275 2349,275 2399,275 2449,275 2499.36,275 1749,276 2549.16,277 2600.05,277 2650,277 2549.56,324.42 1749,325 1799,325 1849,325 1899,325 1949,325 1999,325 2049,325 2099,325 2149,325 2199,325 2249,325 2299,325 2349,325 2399,325 2449,325 2499,325 2599.6,324.84 2649.6,324.84 1697,326 1749,375 1799,375 1849,375 1899,375 1949,375 1999,375 2049,375 2099,375 2149,375 2199,375 2249,375 2299,375 2349,375 2399,375 2449,375 2499,375 2549,375 1697,376 2598.14,376 2648.17,376.42 2698.17,376.42 1749,425 1799,425 1849,425 1899,425 1949,425 1999,425 2049,425 2099,425 2149,425 2199,425 2249,425 2299,425 2349,425 2399,425 2449,425 2499,425 2549,425 2599,425 2649.03,425.43 2699.03,425.43 1697,426 2750.73,426 1749,475 1799,475 1849,475 1899,475 1949,475 1999,475 2049,475 2099,475 2149,475 2199,475 2249,475 2299,475 2349,475 2399,475 2449,475 2499,475 2549,475 2599,475 2649,475 2699,475 2749,475 2799,475 2849,475 2899,475 2951,475 1697,476 2549,525 2599,525 2649,525 2699,525 2749,525 2799,525 2849,525 2899,525 2951,525 1748,526 1798,526 1848,526 1898,526 1948,526 1998,526 2048,526 2098,526 2148,526 2198,526 2248,526 2298,526 2348,526 2398,526 2448,526 2499.56,526 1695.91,529 2549,575 2599,575 2649,575 2699,575 2749,575 2799,575 2849,575 2899,575 2951,575 2499.56,576 2549,625 2599,625 2649,625 2699,625 2749,625 2799,625 2849,625 2899,625 2951,625 2499.56,626 2549,675 2599,675 2649,675 2699,675 2749,675 2799,675 2849,675 2899,675 2951,675 2499.56,676 2549,725 2599,725 2649,725 2699,725 2749,725 2799,725 2849,725 2899,725 2951,725 2499.56,726 2549,775 2599,775 2649,775 2699,775 2749,775 2799,775 2849,775 2899,775 2951,775 2499.56,776 2549,825 2599,825 2649,825 2699,825 2749,825 2799,825 2849,825 2899,825 2951,825 2499.56,826 2799.89,876.76 2849.13,877.4 2950.89,876.76 2547.35,877.76 2649.49,877.76 2698.73,878.4 2748.4,878.38 2899.4,878.38 2497.91,878.76 2598,879.38
NetC67_2: C67.2 C68.1 D4.3 R48.1 R50.2 R51.2 | length 752.8
  Top Layer w10: R51.2@2601,1191 R50.2@2662,1191 ; v1(2663,1166) R50.2@2663,1190
  Signal Layer 2 w10: v1(2057,1060.91) 2079.67,1060.91 2206.76,1188 2641,1188 v1(2663,1166)
  other v4: 1806,589 1728.12,590 1653,591 1652,633.15 1728.8,633.15 1805,633 1805,688 1652,690 1728.12,690 1728.12,746 1805,746 1652,747
NetC69_1: C69.1 L10.2 Q4.1 Q4.2 Q4.3
NetC70_1: C70.1 L11.2 Q4.5 Q4.6 Q4.7 Q4.8 Q4.9 | length 98.2
  Top Layer w40: 894,632 930,596 930,582.36 896.39,582.36
NetC71_1: C71.1 R14.1 U6.12 | length 361.8
  Top Layer w7: C71.1@2322.62,1322 2357,1322 2396,1283 ; R14.1@2325.62,1224 2361,1224 2396,1259 2396,1283 ; U6.12@2517.16,1345.27 2517.16,1325.84 2517,1325.68 2517,1317 2483,1283 2396,1283
NetC75_2: C75.2 R53.2 U6.18 | length 322.2
  Top Layer w10: U6.18@2621.49,1390.55 2686.21,1390.55 2703.38,1373.38 C75.2@2743.76,1373.38 ; C75.2@2744,1373.62 2786.38,1373.62 2844,1316 R53.2@2844,1247
NetC78_1: C78.1 L12.1 Q6.5 Q6.6 Q6.7 Q6.8 Q6.9
NetC78_2: C78.2 Q6.4 R57.2 R66.1
NetC79_1: C79.1 L6.1 R29.2 R34.2 | length 342.1
  Top Layer w50: L6.1@1795.96,2774 1848.05,2826.09 1916,2826.09 R29.2@2032.4,2826.09 ; R34.2@2048.91,2725.48 R29.2@2048.91,2809.57
NetC85_1: C85.1 L10.1 R48.2 R52.2 | length 972
  Top Layer w10: v1(2433,1214) 2441,1214 2469,1186 R52.2@2472,1189
  Top Layer w20: R48.2@1922,849.91 1937,834.91
  Top Layer w30: v2(975,311) 976,310 976.51,310.51 L10.1@982.02,305 ; v2(1922,799) v2@1922,819.91
  Top Layer w40: v2@979.96,242.96 L10.1@979.96,306.04 ; L10.1@982.02,305 v2(1039,305) v2@1044,305
  Signal Layer 2 w10: v2@1989,802 2013,826 2013,1045.2 2049.8,1082 2071.87,1082 2203.87,1214 v1(2433,1214)
  other v2: 976,239 1992,802 2062,802
NetC86_1: C86.1 R14.2 | length 66.8
  Top Layer w10: R14.2@2278.38,1224 C86.1@2325.62,1271.24
NetC87_1: C87.1 R70.2 | length 52
  Top Layer w7: R70.2@2378,1650.38 C87.1@2430,1650.38
NetJ1_1: J1.1 R1.1 | length 353.9
  Top Layer w20: R1.1@189.14,1940.63 168.63,1940.63 137,1909 137,1725 166.36,1695.64 J1.1@229.46,1695.64
NetJ1_2: J1.2 R4.1 | length 258.6
  Top Layer w7: R4.1@236.38,1850.63 304.87,1850.63 389.7,1765.8 J1.2@389.7,1695.64
NetJ1_4: J1.4 R5.1 | length 98.8
  Top Layer w10: J1.4@389.7,1645.64 487.94,1645.64 R5.1@488.31,1646
NetJ1_6: J1.6 R6.1 | length 98.8
  Top Layer w10: J1.6@389.7,1595.64 487.94,1595.64 R6.1@488.31,1596
NetJ1_8: J1.8 R7.1 | length 102.7
  Top Layer w10: J1.8@389.57,1546.26 R7.1@492.26,1546.26
NetL1_2: L1.2 U2.5 | length 116.2
  Top Layer w15: U2.5@284.39,910.28 308.72,910.28 326.99,892.01 L1.2@393,892.01
NetL2_1: L2.1 U3.6 | length 83.3
  Top Layer w10: U3.6@406.35,1286 486.55,1286 L2.1@488.28,1287.72 ; L2.1@519.82,1267.27 L2.1@520.28,1267.72
NetL2_4: L2.4 U3.7 | length 99.4
  Top Layer w10: U3.7@406.35,1336 446,1336 L2.4@488.28,1378.28
NetQ1_4: Q1.4 U7.5 | length 224.3
  Top Layer w10: Q1.4@1719,1504.5 1752.5,1504.5 1864.69,1392.31 U7.5@1896.83,1392.31
NetQ2_4: Q2.4 R40.1 | length 153.3
  Top Layer w10: R40.1@1387.76,2638.63 1387.76,2571.63 1427.51,2531.87 Q2.4@1457.61,2531.87
NetQ3_1: Q3.1 Q3.2 Q3.3 R36.1 R38.2 | length 293.5
  Top Layer w10: v1(2710,1855) 2710,1794.76 2711.31,1793.45 ; R36.1@2756,1642.62 v1(2756,1687)
  Signal Layer 1 w10: v1(2710,1855) 2710,1733 v1(2756,1687)
NetQ3_4: Q3.4 R30.1 | length 330.4
  Top Layer w10: Q3.4@2573.31,1999 2607,1999 2623,1983 2623,1928 2649,1902 R30.1@2831.31,1902
NetQ4_4: Q4.4 R41.1 | length 75.9
  Top Layer w10: Q4.4@968.39,445.13 1039.87,445.13 R41.1@1043,442
NetQ7_1: Q7.1 R49.1 | length 183.2
  Top Layer w20: Q7.1@2875,1019.06 2875,1126.35 2907,1158.35 R49.1@2907,1189
NetQ7_3: Q7.3 R53.1 R56.2 | length 180.7
  Top Layer w10: 2723,1109 2806,1109 2844,1147 R53.1@2844,1191
NetR16_1: R16.1 U1.59 | length 101.6
  Top Layer w7: U1.59@828.34,1933.99 828.69,1934.34 828.69,1900.1 833,1895.79 833,1836.43 R16.1@832,1835.43
NetR17_1: R17.1 U1.89 | length 114
  Top Layer w7: U1.89@966.49,2371.35 1015.51,2371.35 1029.43,2385.27 R17.1@1074.72,2385.27
NetR18_1: R18.1 U2.4 | length 56.7
  Top Layer w7: R18.1@284.38,828 U2.4@284.39,884.69
NetR24_1: R24.1 U4.2 | length 95.9
  Top Layer w7: R24.1@1210.76,2824.63 1214.44,2828.31 U4.2@1304.64,2828.31 ; R24.1@1210.76,2828.63 R24.1@1211.07,2828.31
NetR30_2: R30.2 U6.22 | length 552
  Top Layer w10: U6.22@2621.49,1469.29 2652.79,1469.29 2696,1512.5 2815.5,1512.5 2831.31,1528.32 R30.2@2831.31,1846
NetR43_1: R43.1 U6.9 | length 145.1
  Top Layer w7: R43.1@2323.62,1371 2360,1371 2385.73,1345.27 U6.9@2458.1,1345.27
NetR47_2: R47.2 U6.32 | length 270.5
  Top Layer w7: R47.2@2257,1648.5 2259.81,1645.69 2259.81,1629.19 2310,1579 2434.5,1579 2458.1,1555.4 U6.32@2458.1,1534.25
NetR49_2: R49.2 U6.19 | length 403.7
  Top Layer w12: U6.19@2621.49,1410.23 2826.77,1410.23 2907,1330 R49.2@2907,1245
NetR59_1: R59.1 U1.44 | length 109.3
  Top Layer w7: R59.1@564.23,1836.69 564.23,1874.23 592.47,1902.47 U1.44@592.47,1934.34
NetR60_1: R60.1 U1.45 | length 93.5
  Top Layer w7: R60.1@608.22,1840.82 U1.45@608.22,1934.34
NetR61_2: R61.2 U1.1 | length 143
  Top Layer w7: R61.2@238.38,2532.63 275.76,2532.63 326.8,2481.58 U1.1@360.19,2481.58
NetR62_2: R62.2 U1.2 | length 129.6
  Top Layer w7: R62.2@238.38,2484.63 257.17,2465.84 U1.2@360.19,2465.84
NetR63_2: R63.2 U1.4 | length 124.6
  Top Layer w7: R63.2@238.2,2440.7 244.56,2434.34 U1.4@360.19,2434.34
NetR72_1: R72.1 U1.24 | length 1786.6
  Top Layer w7: U1.24@360.19,2119.38 429.62,2119.38 v1(438,2111)
  Top Layer w10: v3@442,488 472.38,488 R72.1@473,488.62
  Signal Layer 3 w7: v3(434.88,487.09) 457,509.2 457,1211.38 398,1270.38 398,1749.4 420.23,1771.64 420.23,2093.23 v1(438,2111)
nFLT1: R44.1 U1.76 U6.10 | length 3740.5
  Top Layer w7: U1.76@966.49,2166.62 1009.38,2166.62 v1(1018,2158) ; v1(1223,2155) R44.1@1251.38,2155 ; v1(2478.18,1325.27) U6.10@2478.18,1345.27
  Signal Layer 2 w7: v1(874,698) 1159.8,698 1171.37,709.57 1194.15,709.57 1205.72,698 1435,698 2083.5,1346.5 2384.86,1346.5 2406.09,1325.27 v1(2478.18,1325.27) ; v1(1018,2158) 1032.57,2158 1056.7,2182.13 1169.42,2182.13 1196.55,2155 v1(1223,2155)
  Signal Layer 3 w7: v1(874,698) 874,780.29 874.76,781.05 874.76,1530.76 886.62,1542.62 886.62,2026.62 v1(1018,2158)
